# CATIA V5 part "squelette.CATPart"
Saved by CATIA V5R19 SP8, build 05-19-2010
Part number: squelette
Bounding box of the stored display mesh (mm): x 0 to 10, y 284.205 to 471.633, z 69.637 to 432
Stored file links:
  C:\Users\thinkmotion1\Desktop\IAO OK\IAO_2010_1458_splanchena\Correction_Khaled\squelette.CATPart
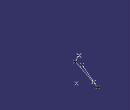
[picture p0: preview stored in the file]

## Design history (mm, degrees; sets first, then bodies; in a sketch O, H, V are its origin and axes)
Set1
  Point1: (0, 330, 432)
  Plane1: type Offset, RefPlane yz-plane, Offset 5
  Point2: type OnPlane, Support Plane1, H 330, V 432, Direction (0, 1, 0)
  Point3: type OnPlane, Support Plane1, H 288.708, V 69.637, Direction (0, 1, 0)
  Point4: type OnPlane, Support Plane1, H 335.33, V 228.44, Direction (0, 1, 0)
  Line1: type PtPt, FirstPoint Point2, SecondPoint Point3, Support Plane1
  Point5: type OnPlane, Support yz-plane, H 112.203, V 476.664, Direction (0, 1, 0)
  Line2: type PtPt, FirstPoint Point5, SecondPoint Point1, Support yz-plane
  Line3: type PtPt, FirstPoint Point1, SecondPoint Point2
  Plane2: type Offset, RefPlane yz-plane, Offset 10
  Point6: type OnPlane, Support Plane2, H 284.205, V 229.954, Direction (0, 1, 0)
  Point7: type OnPlane, Support Plane2, H 313.502, V 287.224, Direction (0, 1, 0)
  Point8: type OnPlane, Support Plane2, H 471.633, V 136.24, Direction (0, 1, 0)
  Line4: type PtPt, FirstPoint Point8, SecondPoint Point6, Support Plane2
  Line5: type PtPt, FirstPoint Point6, SecondPoint Point7, Support Plane2
  Point9: type OnPlane, Support Plane1, H 435.422, V 154.346, Direction (0, 1, 0)
  Line6: type PtPt, FirstPoint Point4, SecondPoint Point9, Support Plane1
  Point10: type OnPlane, Support Plane2, H 434.542, V 154.998, Direction (0, 1, 0)
  Line7: type PtPt, FirstPoint Point9, SecondPoint Point10
  Point11: type OnPlane, Support Plane1, H 313.502, V 287.224, Direction (0, 1, 0)
  Line8: type PtPt, FirstPoint Point11, SecondPoint Point7
Body1 (main body)
  Sketch1 on yz-plane, origin (0, 0, 0), H (0, 1, 0), V (0, 0, 1)
    point P1 (221.6772, 16.7757)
